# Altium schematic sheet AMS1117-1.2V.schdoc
size 127 x 101 mm
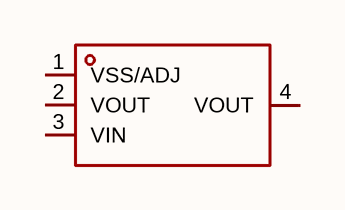
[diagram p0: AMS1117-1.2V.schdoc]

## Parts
U?  ams1117-1.2v  [SOT-223-4_L6.5-W3.5-P2.30-LS7.0-BR]  (value not drawn)

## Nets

Not connected (* = marked no-connect by the designer): U? 1(VSS/ADJ) 2(VOUT) 3(VIN) 4(VOUT)

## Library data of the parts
U? = ams1117-1.2v: 输出极性:正极;工作电压:15V;输出电压:1.2V;输出电流:1.2A;电源纹波抑制比(PSRR):-;输出类型:固定;; Manufacturer: JSMSEMI(杰盛微); AddInBom: yes; ModelId: 925194bf9823436183a3e0b978a8d076; ModelName: SOT-223-4P_L6.5-W3.5-H1.6-LS7.0-P2.30; ModelTransform: 279.89794,255.905,0,180,0,0,-0.0005,-0.0005,0; Output Configuration: 正极; Voltage - Supply: 15V; Output Voltage: 1.2V; Output Current: 1.2A; Voltage Dropout: 1.3V@(800mA); standby current: 2mA; Output Type: 固定; Number of Outputs: 1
